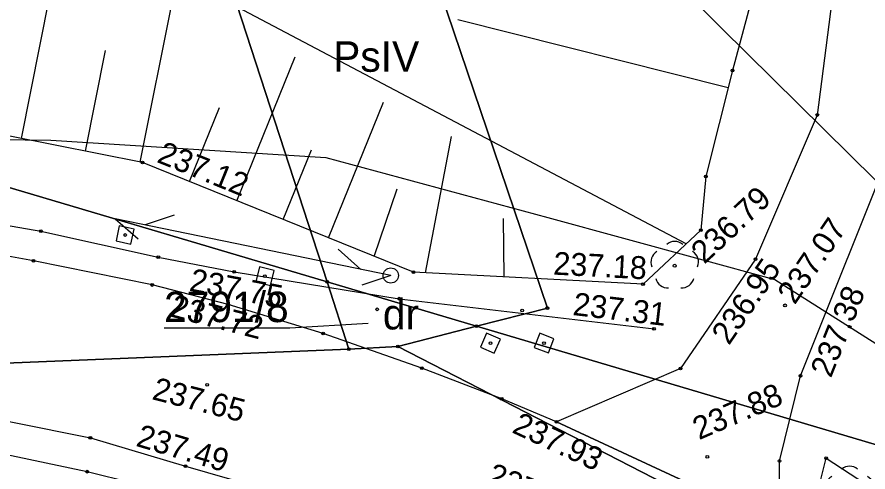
# Model space of a CAD drawing. Extents: x 6596400 to 6597200, y 5539751 to 5540251.
# Drawn here: x 6596788.23 to 6596816.16, y 5540075.21 to 5540090.15 of the extents above; entities that cross this region are included whole.
import ezdxf

# ---------------------------------------------------------------- set-up
doc = ezdxf.new("R2010")
doc.units = 0
for name, color, linetype in [('000 Inne (niezydentyfikowane)', 7, 'Continuous'), ('140-Punkty robocze', 7, 'Continuous'), ('203-punkt graniczny', 7, 'Continuous'), ('209-oznaczenie konturu klasyfikacyjnego', 7, 'Continuous'), ('210-oznaczenie konturu użytku gruntowego', 7, 'Continuous'), ('211-numer działki ewidencyjnej', 7, 'Continuous'), ('217-kontur klasyfikacyjny', 7, 'Continuous'), ('218-kontur użytku gruntowego', 7, 'Continuous'), ('219-działka ewidencyjna', 7, 'Continuous'), ('bariera ochronna', 7, 'Continuous'), ('drzewo liściaste', 7, 'Continuous'), ('jezdnia', 7, 'Continuous'), ('Linia obszaru zagospodarowania terenu', 7, 'Continuous'), ('obudowa ochronna przewodu', 7, 'Continuous'), ('pikieta sztuczna', 7, 'Continuous'), ('pikieta sztuczna-Atr2', 7, 'Continuous'), ('przewód telekomunikacyjny napowietrzny', 7, 'Continuous'), ('przewód telekomunikacyjny podziemny', 7, 'Continuous'), ('skarpa nieumocniona', 7, 'Continuous'), ('słup przewodów napowietrznych', 7, 'Continuous'), ('właz do komory lub kanału - kwadratowy', 7, 'Continuous')]:
    doc.layers.add(name, color=color, linetype=linetype)

# ---------------------------------------------------------------- blocks, each defined once
blk = doc.blocks.new('203')
blk.add_circle((0, 0), 0.045)
blk = doc.blocks.new('OP021')
blk.add_circle((0, 0), 0.05)
for centre, start, end in [((0, 0.4), 49.272, 130.728), ((-0.38, 0.124), 121.308, 202.548), ((0.38, 0.124), 337.452, 58.692), ((-0.235, -0.324), 193.221, 274.871), ((0.235, -0.324), 265.129, 346.779)]:
    blk.add_arc(centre, 0.4, start, end)
blk = doc.blocks.new('US15')
blk.add_circle((0, 0), 0.25)
blk = doc.blocks.new('SUTP')
for p, q in [((0, 0), (0.866, 0.5)), ((9.232, 0), (8.366, 0.5)), ((0, 0), (9.232, 0)), ((1.866, -0.5), (1, 0)), ((7.366, -0.5), (8.232, 0))]:
    blk.add_line(p, q)
blk = doc.blocks.new('US22A')
blk.add_lwpolyline([(-0.25, -0.25), (0.25, -0.25), (0.25, 0.25), (-0.25, 0.25)], close=True)
blk = doc.blocks.new('PIKIETA')
blk.add_circle((0, 0), 0.045)
blk = doc.blocks.new('PW01')
blk.add_circle((0, 0), 0.045)

msp = doc.modelspace()

# ---------------------------------------------------------------- linework, layer by layer
at = {"layer": '000 Inne (niezydentyfikowane)'}
for p, q in [((6596788.38, 5540086.16), (6596789.7, 5540092.84)), ((6596810.2, 5540082.7), (6596792, 5540092.31)), ((6596792.28, 5540085.38), (6596793.38, 5540090.9)), ((6596811.57, 5540087.82), (6596802.7, 5540090.06)), ((6596790.48, 5540085.74), (6596791.14, 5540089.05)), ((6596795.45, 5540084.11), (6596797.36, 5540088.84)), ((6596798.46, 5540082.9), (6596800.26, 5540087.35)), ((6596793.89, 5540084.75), (6596794.88, 5540087.18)), ((6596801.64, 5540081.75), (6596802.49, 5540086.22)), ((6596796.97, 5540083.5), (6596797.9, 5540085.79)), ((6596799.96, 5540082.29), (6596800.71, 5540084.51)), ((6596804.22, 5540081.62), (6596804.2, 5540083.53))]:
    msp.add_line(p, q, dxfattribs=at)
at = {"layer": '211-numer działki ewidencyjnej'}
msp.add_lwpolyline([(6596799.76, 5540080.08), (6596797.19, 5540079.93), (6596793.059, 5540079.93)], dxfattribs=at)
at = {"layer": '217-kontur klasyfikacyjny'}
for points in [[(6596805.64, 5540080.59), (6596797.73, 5540103.94)], [(6596797.73, 5540103.94), (6596805.64, 5540080.59)], [(6596791.71, 5540102.06), (6596798.41, 5540081.45)], [(6596798.41, 5540081.45), (6596791.71, 5540102.06)], [(6596777.15, 5540087.76), (6596798.41, 5540081.45)], [(6596798.41, 5540081.45), (6596803.31, 5540080)], [(6596803.31, 5540080), (6596805.64, 5540080.59)], [(6596805.64, 5540080.59), (6596803.31, 5540080)], [(6596803.31, 5540080), (6596818.76, 5540075.41)]]:
    msp.add_lwpolyline(points, dxfattribs=at)
at = {"layer": '218-kontur użytku gruntowego'}
for points in [[(6596805.64, 5540080.59), (6596797.73, 5540103.94)], [(6596797.73, 5540103.94), (6596805.64, 5540080.59)], [(6596791.71, 5540102.06), (6596798.41, 5540081.45)], [(6596798.41, 5540081.45), (6596791.71, 5540102.06)], [(6596777.15, 5540087.76), (6596798.41, 5540081.45)], [(6596798.41, 5540081.45), (6596777.15, 5540087.76)], [(6596798.41, 5540081.45), (6596803.31, 5540080)], [(6596798.41, 5540081.45), (6596799.12, 5540079.24)], [(6596803.31, 5540080), (6596798.41, 5540081.45)], [(6596799.12, 5540079.24), (6596798.41, 5540081.45)], [(6596803.31, 5540080), (6596805.64, 5540080.59)], [(6596805.64, 5540080.59), (6596803.31, 5540080)], [(6596803.31, 5540080), (6596800.73, 5540079.33)], [(6596800.73, 5540079.33), (6596803.31, 5540080)], [(6596818.76, 5540075.41), (6596803.31, 5540080)], [(6596803.31, 5540080), (6596818.76, 5540075.41)], [(6596783.29, 5540078.6), (6596799.12, 5540079.24)], [(6596799.12, 5540079.24), (6596783.29, 5540078.6)], [(6596799.12, 5540079.24), (6596800.73, 5540079.33)], [(6596800.73, 5540079.33), (6596799.12, 5540079.24)], [(6596800.73, 5540079.33), (6596813.3, 5540072.86)], [(6596813.3, 5540072.86), (6596800.73, 5540079.33)]]:
    msp.add_lwpolyline(points, dxfattribs=at)
at = {"layer": '219-działka ewidencyjna'}
for points in [[(6596805.64, 5540080.59), (6596797.73, 5540103.94)], [(6596798.41, 5540081.45), (6596791.71, 5540102.06)], [(6596798.41, 5540081.45), (6596777.15, 5540087.76)], [(6596799.12, 5540079.24), (6596798.41, 5540081.45)], [(6596803.31, 5540080), (6596798.41, 5540081.45)], [(6596803.31, 5540080), (6596805.64, 5540080.59)], [(6596800.73, 5540079.33), (6596803.31, 5540080)], [(6596818.76, 5540075.41), (6596803.31, 5540080)], [(6596783.29, 5540078.6), (6596799.12, 5540079.24)], [(6596799.12, 5540079.24), (6596800.73, 5540079.33)], [(6596813.3, 5540072.86), (6596800.73, 5540079.33)]]:
    msp.add_lwpolyline(points, dxfattribs=at)
at = {"layer": 'bariera ochronna'}
for points in [[(6596724.82, 5540100.27), (6596724.21, 5540095.84), (6596728.33, 5540094.88), (6596750, 5540090.55), (6596759.32, 5540088.76), (6596768.42, 5540087.04), (6596777.66, 5540085.28), (6596786.8, 5540083.5), (6596789.01, 5540083.12), (6596792.87, 5540082.26), (6596795.36, 5540081.78), (6596800.78, 5540080.9), (6596809.14, 5540079.91)], [(6596774.86, 5540078.28), (6596785.35, 5540076.32), (6596790.54, 5540075.22), (6596793.53, 5540074.48), (6596795.64, 5540073.93), (6596798.3, 5540073.09), (6596802.06, 5540071.69), (6596807.84, 5540069.06), (6596812.67, 5540066.17), (6596814.81, 5540064.78), (6596821.33, 5540060.18), (6596825.095, 5540057.67)]]:
    msp.add_lwpolyline(points, dxfattribs=at)
at = {"layer": 'jezdnia'}
for points in [[(6596816.136, 5540099.702), (6596814.5, 5540086.93), (6596812.47, 5540082.2), (6596810.01, 5540078.61), (6596805.94, 5540076.86), (6596810.44, 5540074.77), (6596813.26, 5540073.35), (6596813.26, 5540075.57), (6596813.95, 5540078.37), (6596817.04, 5540086.1), (6596818.162, 5540098.968)], [(6596828.719, 5540062.578), (6596825.42, 5540065.32), (6596821.78, 5540067.97), (6596818.46, 5540070.24), (6596813.26, 5540073.35), (6596810.44, 5540074.77), (6596805.94, 5540076.86), (6596804.14, 5540077.61), (6596801.52, 5540078.62), (6596798.28, 5540079.76), (6596795.16, 5540080.71), (6596792.67, 5540081.35), (6596788.77, 5540082.14), (6596786.6, 5540082.54), (6596777.46, 5540084.34), (6596768.21, 5540086.12), (6596759.17, 5540087.8), (6596749.8, 5540089.83), (6596749.82, 5540090.44), (6596743.18, 5540091.67), (6596739.76, 5540092.34), (6596735.83, 5540093.08), (6596728.26, 5540094.5), (6596723.35, 5540095.14)], [(6596748.72, 5540084.9), (6596758.31, 5540082.61), (6596767.09, 5540080.95), (6596776.43, 5540079.11), (6596785.57, 5540077.35), (6596790.64, 5540076.33), (6596793.76, 5540075.4), (6596796, 5540074.75), (6596799.11, 5540073.89), (6596802.37, 5540072.55), (6596804.34, 5540071.72), (6596806.42, 5540070.73), (6596808.2, 5540069.72), (6596810.28, 5540068.61), (6596812.76, 5540067.19), (6596815.5, 5540065.85), (6596818.95, 5540063.45), (6596822.11, 5540061.14), (6596825.559, 5540058.298)]]:
    msp.add_lwpolyline(points, dxfattribs=at)
at = {"layer": 'Linia obszaru zagospodarowania terenu'}
msp.add_lwpolyline([(6596664.616, 5540132.112), (6596671.21, 5540127.95), (6596681.8, 5540121.54), (6596690.35, 5540115.69), (6596701.61, 5540105.97), (6596709.34, 5540098.61), (6596715.39, 5540091.82), (6596718.63, 5540088.53), (6596721.87, 5540084.71), (6596726.1, 5540083.21), (6596730.7, 5540082.79), (6596730.91, 5540075), (6596745.51, 5540074.64), (6596746.77, 5540082.74), (6596765.15, 5540085.09), (6596776.62, 5540086.27), (6596789.34, 5540086.1), (6596798.37, 5540085.54), (6596805.65, 5540083.56), (6596813.11, 5540081.53), (6596819.41, 5540077.54), (6596826.58, 5540072.81), (6596832.721, 5540067.998)], dxfattribs=at)
at = {"layer": 'obudowa ochronna przewodu'}
msp.add_lwpolyline([(6596793.213, 5540107.981), (6596811.35, 5540089.78), (6596822.295, 5540078.976)], dxfattribs=at)
at = {"layer": 'przewód telekomunikacyjny podziemny'}
msp.add_lwpolyline([(6596822.295, 5540078.976), (6596811.35, 5540089.78), (6596793.213, 5540107.981)], dxfattribs=at)
at = {"layer": 'skarpa nieumocniona'}
msp.add_lwpolyline([(6596783.42, 5540094.18), (6596788.65, 5540093.09), (6596792.84, 5540092.11), (6596803.9, 5540094.29), (6596807.46, 5540098.95), (6596807.73, 5540101.08), (6596804.41, 5540103.26), (6596804.73, 5540103.83), (6596814.59, 5540100.26), (6596813.45, 5540094.85), (6596811.72, 5540088.39), (6596810.84, 5540084.91), (6596810.68, 5540083.15), (6596808.78, 5540081.38), (6596801.25, 5540081.77), (6596792.35, 5540085.37), (6596783.74, 5540087.08)], dxfattribs=at)
msp.add_lwpolyline([(6596783.42, 5540094.18), (6596788.65, 5540093.09), (6596792.84, 5540092.11), (6596803.9, 5540094.29), (6596807.46, 5540098.95), (6596807.73, 5540101.08), (6596804.41, 5540103.26), (6596804.73, 5540103.83), (6596814.59, 5540100.26), (6596813.45, 5540094.85), (6596811.72, 5540088.39), (6596810.84, 5540084.91), (6596810.68, 5540083.15), (6596808.78, 5540081.38), (6596801.25, 5540081.77), (6596792.35, 5540085.37), (6596783.74, 5540087.08)], dxfattribs=at)
msp.add_lwpolyline([(6596820.02, 5540072.25), (6596827.3, 5540067.41), (6596830.4, 5540064.86), (6596828.96, 5540062.91), (6596825.72, 5540065.66), (6596819.57, 5540070.37), (6596814.45, 5540074.31), (6596814.79, 5540075.66)], close=True, dxfattribs=at)
msp.add_lwpolyline([(6596820.02, 5540072.25), (6596827.3, 5540067.41), (6596830.4, 5540064.86), (6596828.96, 5540062.91), (6596825.72, 5540065.66), (6596819.57, 5540070.37), (6596814.45, 5540074.31), (6596814.79, 5540075.66)], close=True, dxfattribs=at)

# ---------------------------------------------------------------- block references
at = {"layer": '140-Punkty robocze'}
for p in [(6596811.72, 5540088.39), (6596814.5, 5540086.93), (6596810.84, 5540084.91), (6596789.01, 5540083.12), (6596791.78, 5540082.99), (6596792.87, 5540082.26), (6596788.77, 5540082.14), (6596796.37, 5540081.64), (6596801.25, 5540081.77), (6596792.67, 5540081.35), (6596800.78, 5540080.9), (6596800.05, 5540080.55), (6596804.81, 5540080.51), (6596798.28, 5540079.76), (6596803.77, 5540079.44), (6596805.53, 5540079.44), (6596801.52, 5540078.62), (6596810.01, 5540078.61), (6596804.14, 5540077.61), (6596790.64, 5540076.33), (6596813.26, 5540075.57), (6596814.79, 5540075.66), (6596790.54, 5540075.22)]:
    msp.add_blockref('PIKIETA', p, dxfattribs=at)
at = {"layer": '203-punkt graniczny'}
for p in [(6596798.41, 5540081.45), (6596805.64, 5540080.59), (6596803.31, 5540080), (6596799.12, 5540079.24), (6596800.73, 5540079.33)]:
    msp.add_blockref('203', p, dxfattribs=at)
at = {"layer": 'drzewo liściaste'}
for p in [(6596809.82, 5540081.98), (6596815.56, 5540074.6)]:
    msp.add_blockref('OP021', p, dxfattribs=at)
at = {"layer": 'pikieta sztuczna'}
for p in [(6596792.35, 5540085.37), (6596810.68, 5540083.15), (6596812.47, 5540082.2), (6596795.36, 5540081.78), (6596808.78, 5540081.38), (6596795.16, 5540080.71), (6596813.44, 5540080.68), (6596809.14, 5540079.91), (6596813.95, 5540078.37), (6596794.47, 5540078.07), (6596805.94, 5540076.86), (6596810.89, 5540075.71), (6596793.76, 5540075.4)]:
    msp.add_blockref('PW01', p, dxfattribs=at)
at = {"layer": 'przewód telekomunikacyjny napowietrzny', "rotation": 168.334}
msp.add_blockref('SUTP', (6596800.5, 5540081.66), dxfattribs=at)
at = {"layer": 'słup przewodów napowietrznych'}
msp.add_blockref('US15', (6596800.5, 5540081.66), dxfattribs=at)
at = {"layer": 'właz do komory lub kanału - kwadratowy'}
for p, rotation in [((6596791.78, 5540082.99), 167.905), ((6596796.37, 5540081.64), 166.21400000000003), ((6596803.77, 5540079.44), 156.218), ((6596805.53, 5540079.44), -21.250999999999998)]:
    msp.add_blockref('US22A', p, dxfattribs=dict(at, rotation=rotation))

# ---------------------------------------------------------------- texts
at = {"layer": '209-oznaczenie konturu klasyfikacyjnego'}
msp.add_text('PsIV', height=1, dxfattribs=at).set_placement((6596798.61, 5540088.35))
at = {"layer": '210-oznaczenie konturu użytku gruntowego'}
msp.add_text('dr', height=1, dxfattribs=at).set_placement((6596800.24, 5540079.89))
at = {"layer": '211-numer działki ewidencyjnej'}
msp.add_text('2791/8', height=1, dxfattribs=at).set_placement((6596793.059, 5540080.13))
at = {"layer": 'pikieta sztuczna-Atr2'}
for s, rotation, p in [('237.12', 337.977, (6596792.789, 5540085.395)), ('236.79', 42.971, (6596810.791, 5540082.011)), ('237.07', 55.58, (6596813.759, 5540080.676)), ('237.18', 357.035, (6596805.821, 5540081.691)), ('236.95', 55.58, (6596811.599, 5540079.346)), ('237.75', 349.089, (6596793.858, 5540081.164)), ('237.38', 68.211, (6596814.946, 5540078.272)), ('237.72', 345.585, (6596793.223, 5540080.324)), ('237.31', 353.246, (6596806.452, 5540080.365)), ('237.65', 345.585, (6596792.633, 5540077.604)), ('237.88', 23.267, (6596810.616, 5540076.251)), ('237.93', 335.088, (6596804.444, 5540076.52)), ('237.49', 343.402, (6596792.106, 5540076.071)), ('237.79', 337.38, (6596803.602, 5540074.838))]:
    msp.add_text(s, height=0.75, rotation=rotation, dxfattribs=at).set_placement(p)

doc.saveas('drawing.dxf')
